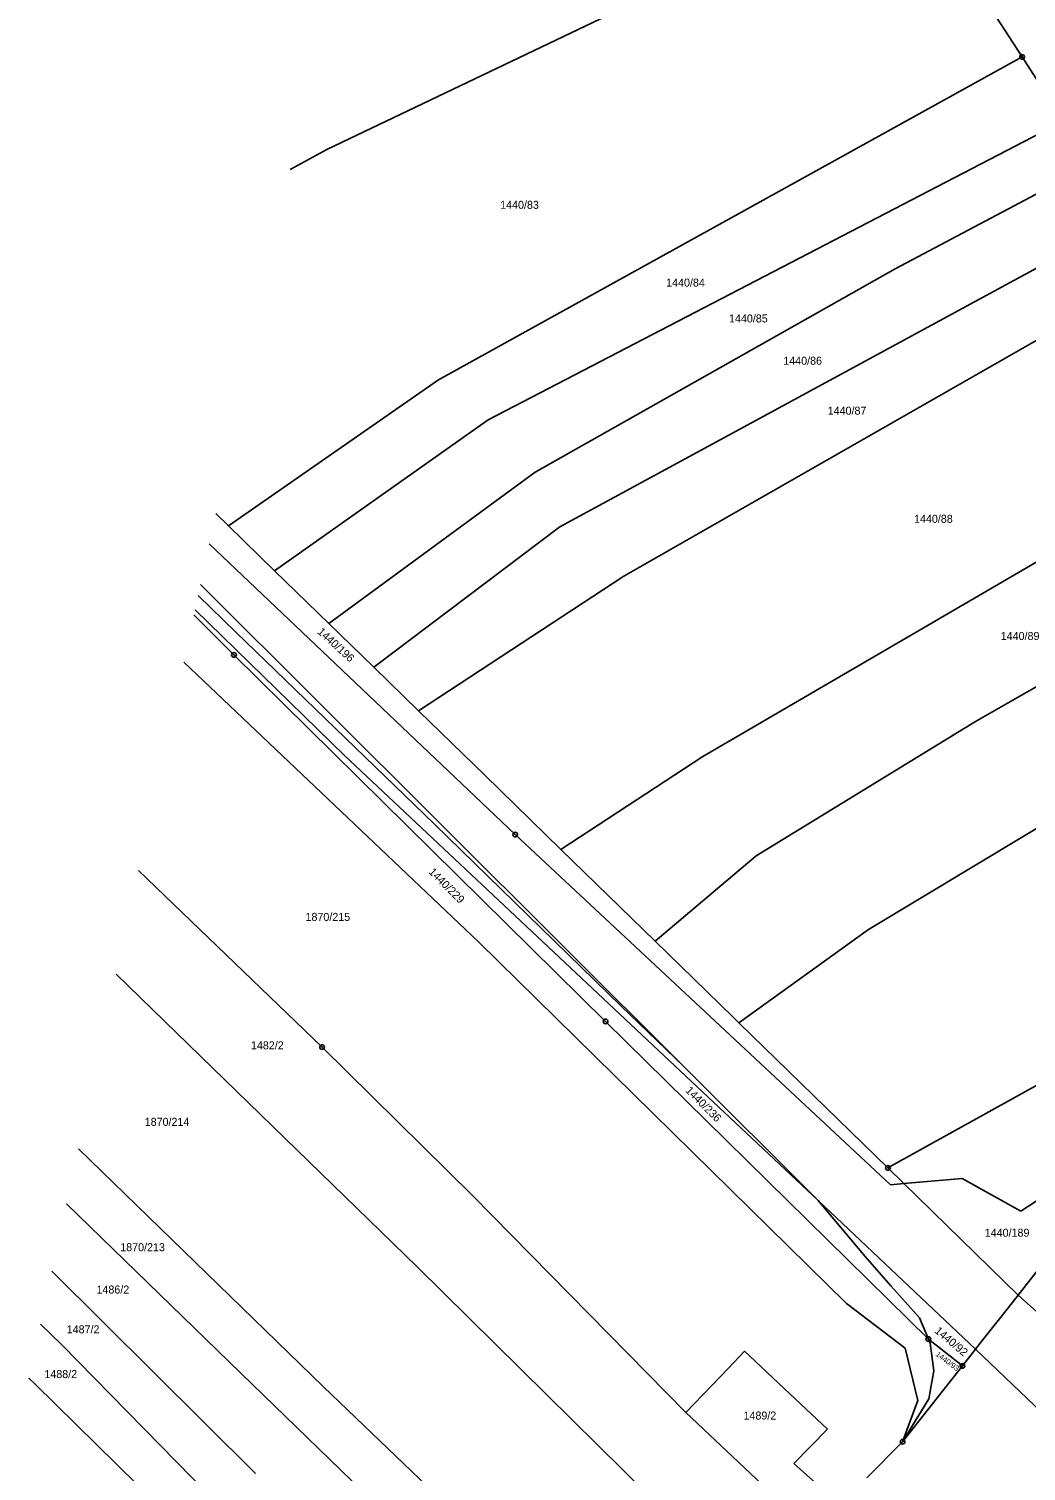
# Model space of a CAD drawing. Extents: x -779596 to -776743, y -1030330 to -1024513.
# Drawn here: x -779160.4 to -778948.7, y -1029994.5 to -1029688.2 of the extents above; entities that cross this region are included whole.
import ezdxf

# ---------------------------------------------------------------- set-up
doc = ezdxf.new("R2010")
doc.units = 0
for name, color, linetype in [('hranice parcel', 7, 'Continuous'), ('Kód', 7, 'Continuous'), ('č_parcel poz_', 7, 'Continuous')]:
    doc.layers.add(name, color=color, linetype=linetype)

msp = doc.modelspace()

# ---------------------------------------------------------------- linework, layer by layer
at = {"layer": 'hranice parcel'}
for points in [[(-778998.32, -1029666.59), (-779097.19, -1029713.87)], [(-778949.56, -1029694.2), (-778955.2, -1029685.46)], [(-779073.43, -1029762.82), (-778949.56, -1029694.2)], [(-778941.82, -1029706.21), (-778949.56, -1029694.2)], [(-778940.02, -1029707.45), (-779062.92, -1029771.31)], [(-779097.19, -1029713.87), (-779104.923, -1029718.154)], [(-778976.49, -1029739.22), (-778929.87, -1029714.49)], [(-778917.27, -1029723.22), (-779047.72, -1029794.02)], [(-779034.09, -1029804.49), (-778905.83, -1029731.14)], [(-779052.95, -1029782.39), (-778976.49, -1029739.22)], [(-779118.07, -1029793.76), (-779073.43, -1029762.82)], [(-779062.92, -1029771.31), (-779108.25, -1029803.31)], [(-779096.72, -1029814.54), (-779052.95, -1029782.39)], [(-779120.72, -1029791.18), (-779118.07, -1029793.76)], [(-778928.93, -1029791.22), (-779017.32, -1029842.78)], [(-779118.07, -1029793.76), (-779108.25, -1029803.31)], [(-779047.72, -1029794.02), (-779087.22, -1029823.79)], [(-779122.117, -1029797.637), (-779057.16, -1029859.36)], [(-779108.25, -1029803.31), (-779096.72, -1029814.54)], [(-779123.986, -1029806.274), (-779021.3, -1029908.69)], [(-779077.69, -1029833.07), (-779034.09, -1029804.49)], [(-779124.482, -1029808.569), (-779116.48, -1029816.34)], [(-778959.44, -1029835.36), (-778910.41, -1029807.31)], [(-779125.372, -1029812.681), (-779116.88, -1029821.21)], [(-779093.45, -1029842.56), (-779125.141, -1029811.616)], [(-779096.72, -1029814.54), (-779087.22, -1029823.79)], [(-779116.48, -1029816.34), (-779074.34, -1029857.13)], [(-779116.88, -1029821.21), (-779038, -1029899.02)], [(-779064.9, -1029882.19), (-779127.541, -1029822.71)], [(-779087.22, -1029823.79), (-779077.69, -1029833.07)], [(-779077.69, -1029833.07), (-779063.65, -1029846.75)], [(-779006.05, -1029863.85), (-778959.44, -1029835.36)], [(-778992.85, -1029937.06), (-779093.45, -1029842.56)], [(-779017.32, -1029842.78), (-779047.48, -1029862.51)], [(-779063.65, -1029846.75), (-779047.48, -1029862.51)], [(-778938.13, -1029853.04), (-778982.14, -1029879.48)], [(-779074.34, -1029857.13), (-779034.66, -1029895.77)], [(-779057.16, -1029859.36), (-778977.53, -1029933.72)], [(-779047.48, -1029862.51), (-779027.45, -1029882.01)], [(-779027.45, -1029882.01), (-779006.05, -1029863.85)], [(-779098.18, -1029904.47), (-779137.12, -1029866.987)], [(-778982.14, -1029879.48), (-779009.69, -1029899.31)], [(-778986.85, -1029958.93), (-779064.9, -1029882.19)], [(-779027.45, -1029882.01), (-779010.96, -1029898.07)], [(-778978.03, -1029930.15), (-778896.1, -1029884.7)], [(-779077.96, -1029951.12), (-779141.888, -1029889.028)], [(-779034.66, -1029895.77), (-779021.3, -1029908.69)], [(-779010.96, -1029898.07), (-779009.69, -1029899.31)], [(-779038, -1029899.02), (-778969.46, -1029966.48)], [(-779009.69, -1029899.31), (-778978.03, -1029930.15)], [(-779098.18, -1029904.47), (-779066.2, -1029936.08)], [(-779021.3, -1029908.69), (-778992.85, -1029937.06)], [(-779097.91, -1029976.63), (-779149.899, -1029926.062)], [(-778978.03, -1029930.15), (-778974.63, -1029933.48)], [(-778977.53, -1029933.72), (-778974.63, -1029933.48)], [(-778974.63, -1029933.48), (-778962.31, -1029932.42)], [(-778950.41, -1029957.13), (-778974.63, -1029933.48)], [(-778962.31, -1029932.42), (-778949.82, -1029939.32)], [(-778949.82, -1029939.32), (-778940.05, -1029932.96)], [(-779152.429, -1029937.757), (-779113.03, -1029976.05)], [(-779020.97, -1029982.11), (-779066.2, -1029936.08)], [(-778982.9, -1029948.96), (-778992.85, -1029937.06)], [(-778992.85, -1029937.06), (-778959.43, -1029968.66)], [(-778934.02, -1029936.29), (-778950.41, -1029957.13)], [(-778977.44, -1029955.17), (-778982.9, -1029948.96)], [(-779112.32, -1029995.05), (-779155.53, -1029952.091)], [(-779077.96, -1029951.12), (-779006.74, -1030021.49)], [(-778971.32, -1029961.97), (-778977.44, -1029955.17)], [(-778974.37, -1029968.39), (-778986.85, -1029958.93)], [(-778957.94, -1029966.75), (-778952.47, -1029959.76)], [(-778952.47, -1029959.76), (-778950.41, -1029957.13)], [(-778950.41, -1029957.13), (-778928.5, -1029976.72)], [(-778969.46, -1029966.48), (-778971.32, -1029961.97)], [(-779153.53, -1029967.64), (-779157.956, -1029963.306)], [(-779118.66, -1030003.16), (-779153.53, -1029967.64)], [(-779008.46, -1029969.07), (-779011.95, -1029972.71)], [(-779007.4, -1029970.07), (-779008.46, -1029969.07)], [(-778971.69, -1029979.54), (-778974.37, -1029968.39)], [(-778969.46, -1029966.48), (-778969.09, -1029967.37)], [(-778969.46, -1029966.48), (-778962.22, -1029972.19)], [(-778968.27, -1029973.26), (-778969.09, -1029967.37)], [(-778962.22, -1029972.19), (-778959.43, -1029968.66)], [(-778959.43, -1029968.66), (-778957.94, -1029966.75)], [(-778959.43, -1029968.66), (-778932.86, -1029994.02)], [(-779000.07, -1029976.96), (-779007.4, -1029970.07)], [(-779159.11, -1029976.04), (-779160.434, -1029974.758)], [(-779011.95, -1029972.71), (-779020.97, -1029982.11)], [(-778962.22, -1029972.19), (-778974.92, -1029988.29)], [(-778969.39, -1029979.2), (-778968.27, -1029973.26)], [(-779059.38, -1030074.18), (-779159.11, -1029976.04)], [(-779113.03, -1029976.05), (-779035.56, -1030051.27)], [(-779027.89, -1030043.75), (-779097.91, -1029976.63)], [(-778990.89, -1029985.59), (-779000.07, -1029976.96)], [(-778974.92, -1029988.29), (-778969.39, -1029979.2)], [(-778974.92, -1029988.29), (-778971.69, -1029979.54)], [(-779020.97, -1029982.11), (-779003.45, -1029998.55)], [(-778998, -1029992.9), (-778990.89, -1029985.59)], [(-778982.54, -1029995.96), (-778974.92, -1029988.29)], [(-778988, -1030001.88), (-778998, -1029992.9)]]:
    msp.add_lwpolyline(points, dxfattribs=at)
at = {"layer": 'Kód'}
for centre, radius in [((-778949.56, -1029694.2), 0.5), ((-778949.56, -1029694.2), 0.032), ((-779116.88, -1029821.21), 0.5), ((-779116.88, -1029821.21), 0.032), ((-779057.16, -1029859.36), 0.5), ((-779057.16, -1029859.36), 0.032), ((-779038, -1029899.02), 0.5), ((-779038, -1029899.02), 0.032), ((-779098.18, -1029904.47), 0.5), ((-779098.18, -1029904.47), 0.032), ((-778978.03, -1029930.15), 0.5), ((-778978.03, -1029930.15), 0.032), ((-778969.46, -1029966.48), 0.5), ((-778969.46, -1029966.48), 0.032), ((-778962.22, -1029972.19), 0.5), ((-778962.22, -1029972.19), 0.032), ((-778974.92, -1029988.29), 0.5), ((-778974.92, -1029988.29), 0.032)]:
    msp.add_circle(centre, radius, dxfattribs=at)

# ---------------------------------------------------------------- texts
at = {"layer": 'č_parcel poz_'}
for s, p in [('1440/83', (-779060.37, -1029726.47)), ('1440/84', (-779025.13, -1029742.99)), ('1440/85', (-779011.78, -1029750.6)), ('1440/86', (-779000.26, -1029759.58)), ('1440/87', (-778990.83, -1029770.18)), ('1440/88', (-778972.5, -1029793.15)), ('1440/89', (-778954.09, -1029818.03)), ('1870/215', (-779101.699, -1029877.689)), ('1482/2', (-779113.28, -1029904.96)), ('1870/214', (-779135.834, -1029921.204)), ('1440/189', (-778957.483, -1029944.75)), ('1870/213', (-779141.032, -1029947.824)), ('1486/2', (-779146.074, -1029956.816)), ('1487/2', (-779152.391, -1029965.264)), ('1488/2', (-779157.137, -1029974.769)), ('1489/2', (-779008.7, -1029983.57))]:
    msp.add_text(s, height=1.7, dxfattribs=at).set_placement(p)
for s, height, rotation, p in [('1440/196', 1.7, 317.60253, (-779099.294, -1029816.472)), ('1440/229', 1.7, 315.10251, (-779075.667, -1029867.431)), ('1440/236', 1.7, 315.00251, (-779021.151, -1029913.836)), ('1440/92', 1.7, 319.90254, (-778968.249, -1029964.976)), ('1440/93', 1.14, 323.30257, (-778968.011, -1029969.95))]:
    msp.add_text(s, height=height, rotation=rotation, dxfattribs=at).set_placement(p)

doc.saveas('drawing.dxf')
